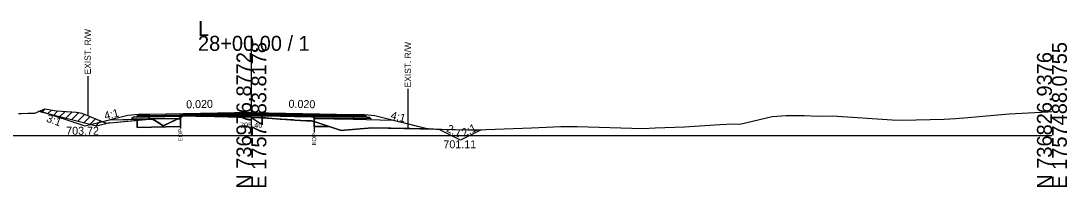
# Model space of a CAD drawing. Extents: x -26 to 4303, y -10 to 9577.
# Drawn here: x 1106.8 to 1302.8, y 7990.3 to 8021.4 of the extents above; entities that cross this region are included whole.
import ezdxf

# ---------------------------------------------------------------- set-up
doc = ezdxf.new("R2010")
doc.units = 0
for name, color, linetype in [('Exist CMT Pavement', 7, 'Continuous'), ('Old_Level_10', 7, 'Continuous'), ('Old_Level_2', 7, 'Continuous'), ('Pattern 1', 7, 'Continuous'), ('Prop CMT Conc Surface', 7, 'Continuous'), ('Prop CMT Concrete Structures', 7, 'Continuous'), ('Prop CMT Concrete Wall', 7, 'Continuous'), ('Prop CMT Pvmt Course 1', 7, 'Continuous'), ('Prop CMT Pvmt Course 1 CG', 7, 'Continuous'), ('Prop CMT Pvmt Course 1 Wedge', 7, 'Continuous'), ('Prop CMT Pvmt Course 2', 7, 'Continuous'), ('Prop CMT Pvmt Course 2 Wedge', 7, 'Continuous'), ('Prop CMT Pvmt Course 3', 7, 'Continuous'), ('Prop CMT Pvmt Surface', 7, 'Continuous'), ('Prop CMT Pvmt Surface Shoulder', 7, 'Continuous'), ('Prop CMT Pvmt Wedge Surface 1', 7, 'Continuous'), ('Prop CMT Pvmt Wedge Surface 2', 7, 'Continuous'), ('Prop CMT Pvmt Wedge Surface 3', 7, 'Continuous'), ('Prop CMT Shld Paved Course 1', 7, 'Continuous'), ('Prop CMT Shld Paved Course 2', 7, 'Continuous'), ('Prop CMT Shld Paved Course 3', 7, 'Continuous'), ('Prop CMT Slope Grass', 7, 'Continuous'), ('Prop CMT Subgrade Earthwork', 7, 'Continuous'), ('Prop Road Sect_ Recs - UC Shallow (Outline)', 7, 'Continuous'), ('Prop Shade Light', 7, 'Continuous'), ('Prop XS DDE Elevations', 7, 'Continuous'), ('Prop XS Ditch Standard Text', 7, 'Continuous'), ('Prop XS Earthwork Shape', 7, 'Continuous'), ('Prop XS Hydro Elevations', 7, 'Continuous'), ('Prop XS SE Text', 7, 'Continuous'), ('Prop XS Side Slope Text', 7, 'Continuous'), ('Prop XS Wedging', 7, 'Continuous')]:
    doc.layers.add(name, color=color, linetype=linetype)

msp = doc.modelspace()

# ---------------------------------------------------------------- linework, layer by layer
at = {"layer": 'Exist CMT Pavement'}
for points in [[(1150, 8004.31), (1130.87, 8003.92)], [(1150, 8004.31), (1169.11, 8003.92)]]:
    msp.add_lwpolyline(points, dxfattribs=at)
at = {"layer": 'Old_Level_10'}
for p, q in [((1185.19, 8001.1), (1183.19, 8001.2)), ((1189.18, 7999.11), (1185.19, 8001.1)), ((1193.07, 8001.05), (1189.18, 7999.11))]:
    msp.add_line(p, q, dxfattribs=at)
at = {"layer": 'Old_Level_2'}
for p, q in [((1150, 8000), (1150, 8018.64)), ((1150, 8000), (1150, 8018.64)), ((1000, 8000), (1150, 8000)), ((1000, 8000), (1150, 8000)), ((1150, 8000), (1300, 8000)), ((1150, 8000), (1300, 8000))]:
    msp.add_line(p, q, dxfattribs=at)
at = {"layer": 'Pattern 1'}
for p, q in [((1110.66, 8004.3), (1111.27, 8004.92)), ((1111.79, 8004.02), (1112.52, 8004.75)), ((1112.92, 8003.74), (1113.76, 8004.57)), ((1114.05, 8003.45), (1115.09, 8004.49)), ((1115.18, 8003.17), (1116.43, 8004.42)), ((1116.32, 8002.89), (1117.7, 8004.28)), ((1117.45, 8002.6), (1118.79, 8003.94)), ((1118.58, 8002.32), (1119.78, 8003.53)), ((1119.71, 8002.04), (1120.78, 8003.11)), ((1120.84, 8001.76), (1121.78, 8002.7)), ((1122.62, 8002.12), (1122.78, 8002.28))]:
    msp.add_line(p, q, dxfattribs=at)
msp.add_lwpolyline([(1121, 8001.72), (1110.11, 8004.44), (1111.33, 8004.94), (1113.49, 8004.59), (1116.23, 8004.43), (1117.2, 8004.37), (1118.22, 8004.18), (1122.8, 8002.27), (1123.44, 8002.33)], close=True, dxfattribs=at)
msp.add_lwpolyline([(1136.69, 8003.35), (1136.69, 8003.11), (1136.19, 8003.1), (1136.69, 8003.35)], dxfattribs=at)
at = {"layer": 'Prop CMT Conc Surface'}
for points in [[(1136.69, 8003.79), (1130.87, 8003.67)], [(1130.87, 8003.67), (1130.87, 8003.47)], [(1130.87, 8003.47), (1136.69, 8003.58)], [(1136.69, 8003.58), (1136.69, 8003.79)], [(1161.75, 8003.61), (1161.75, 8003.82)], [(1161.75, 8003.82), (1169.11, 8003.67)], [(1169.11, 8003.47), (1161.75, 8003.61)], [(1169.11, 8003.67), (1169.11, 8003.47)]]:
    msp.add_lwpolyline(points, dxfattribs=at)
at = {"layer": 'Prop CMT Concrete Structures'}
for points in [[(1130.87, 8003.67), (1130.87, 8003.92)], [(1136.69, 8003.79), (1130.87, 8003.67)], [(1150, 8004.18), (1136.69, 8003.91)], [(1136.69, 8003.91), (1136.69, 8003.79)], [(1150, 8004.18), (1161.75, 8003.95)], [(1161.75, 8003.95), (1161.75, 8003.82)], [(1161.75, 8003.82), (1169.11, 8003.67)], [(1169.11, 8003.67), (1169.11, 8003.92)]]:
    msp.add_lwpolyline(points, dxfattribs=at)
at = {"layer": 'Prop CMT Pvmt Course 1'}
for points in [[(1136.69, 8003.58), (1130.87, 8003.47)], [(1136.69, 8003.25), (1136.69, 8003.58)], [(1161.75, 8003.61), (1169.11, 8003.47)], [(1161.75, 8003.15), (1161.75, 8003.61)], [(1130.87, 8003.47), (1130.87, 8003.13)], [(1130.87, 8003.13), (1136.69, 8003.25)], [(1169.11, 8003.13), (1161.75, 8003.28)], [(1169.11, 8003.47), (1169.11, 8003.13)]]:
    msp.add_lwpolyline(points, dxfattribs=at)
at = {"layer": 'Prop CMT Pvmt Course 1 Wedge'}
for points in [[(1141.82, 8003.56), (1143.12, 8003.59)], [(1150, 8003.4), (1149.52, 8003.45), (1148.34, 8003.42), (1148.13, 8003.42), (1148.13, 8003.42), (1148.11, 8003.42), (1147.61, 8003.43), (1145.68, 8003.47), (1145.63, 8003.47), (1143.25, 8003.54), (1143.12, 8003.55), (1141.82, 8003.56)], [(1143.12, 8003.59), (1143.25, 8003.59), (1145.63, 8003.64), (1145.68, 8003.64), (1147.61, 8003.68), (1148.11, 8003.69), (1148.13, 8003.69), (1148.13, 8003.69), (1148.34, 8003.69), (1149.52, 8003.72), (1150, 8003.73)], [(1150, 8003.73), (1150, 8003.4)], [(1150, 8003.73), (1150.15, 8003.72), (1150.34, 8003.72), (1150.62, 8003.71), (1150.63, 8003.71), (1152.98, 8003.67), (1153.13, 8003.66), (1155.41, 8003.62), (1155.63, 8003.61), (1157.84, 8003.57), (1158.13, 8003.56), (1160.27, 8003.52), (1160.63, 8003.51), (1160.66, 8003.51), (1161.24, 8003.5), (1161.44, 8003.5), (1161.54, 8003.5), (1161.75, 8003.49)], [(1161.75, 8003.49), (1161.75, 8002.57)], [(1136.69, 8003.46), (1136.92, 8003.46)], [(1136.92, 8003.46), (1136.69, 8003.35)], [(1136.69, 8003.35), (1136.69, 8003.46)], [(1161.75, 8002.57), (1161.54, 8002.64), (1161.44, 8002.64), (1161.24, 8002.7), (1160.66, 8002.72), (1160.63, 8002.72), (1160.27, 8002.74), (1158.13, 8002.86), (1157.84, 8002.88), (1155.63, 8003.05), (1155.41, 8003.06), (1153.13, 8003.2), (1152.98, 8003.21), (1150.63, 8003.34), (1150.62, 8003.34), (1150.34, 8003.37), (1150.15, 8003.39), (1150, 8003.4)]]:
    msp.add_lwpolyline(points, dxfattribs=at)
at = {"layer": 'Prop CMT Pvmt Course 2'}
for points in [[(1130.87, 8003.92), (1128.87, 8003.88), (1128.62, 8003.63)], [(1128.62, 8003.63), (1130.87, 8003.67)], [(1130.87, 8003.67), (1130.87, 8003.92)], [(1169.11, 8003.92), (1171.11, 8003.88), (1171.36, 8003.63)], [(1169.11, 8003.67), (1169.11, 8003.92)], [(1171.36, 8003.63), (1169.11, 8003.67)]]:
    msp.add_lwpolyline(points, dxfattribs=at)
at = {"layer": 'Prop CMT Pvmt Course 2 Wedge'}
msp.add_line((1118.87, 8001.72), (1110.38, 8004.55), dxfattribs=at)
for points in [[(1128.87, 8003.88), (1126.87, 8003.72), (1118.87, 8001.72)], [(1171.11, 8003.88), (1173.11, 8003.72), (1183.19, 8001.2)]]:
    msp.add_lwpolyline(points, dxfattribs=at)
at = {"layer": 'Prop CMT Pvmt Course 3'}
for points in [[(1130.87, 8003.67), (1128.62, 8003.63), (1128.4, 8003.42)], [(1130.87, 8003.47), (1130.87, 8003.67)], [(1169.11, 8003.67), (1171.36, 8003.63), (1171.58, 8003.42)], [(1169.11, 8003.47), (1169.11, 8003.67)], [(1128.4, 8003.42), (1130.87, 8003.47)], [(1171.58, 8003.42), (1169.11, 8003.47)]]:
    msp.add_lwpolyline(points, dxfattribs=at)
at = {"layer": 'Prop CMT Pvmt Surface'}
for points in [[(1150, 8004.06), (1130.87, 8003.67)], [(1130.87, 8003.67), (1130.87, 8003.92)], [(1150, 8004.06), (1169.11, 8003.67)], [(1169.11, 8003.67), (1169.11, 8003.92)]]:
    msp.add_lwpolyline(points, dxfattribs=at)
at = {"layer": 'Prop CMT Pvmt Surface Shoulder'}
for points in [[(1136.69, 8003.35), (1137.27, 8003.64), (1137.54, 8003.64), (1138.03, 8003.66), (1140.6, 8003.58), (1140.62, 8003.58), (1140.82, 8003.58), (1143.12, 8003.55), (1143.25, 8003.54), (1145.63, 8003.47), (1145.68, 8003.47), (1147.61, 8003.43), (1148.11, 8003.42), (1148.13, 8003.42), (1148.13, 8003.42), (1148.34, 8003.42), (1149.52, 8003.45), (1150, 8003.4)], [(1150, 8003.4), (1150.15, 8003.39), (1150.34, 8003.37), (1150.62, 8003.34), (1150.63, 8003.34), (1152.98, 8003.21), (1153.13, 8003.2), (1155.41, 8003.06), (1155.63, 8003.05), (1157.84, 8002.88), (1158.13, 8002.86), (1160.27, 8002.74), (1160.63, 8002.72), (1160.66, 8002.72), (1161.24, 8002.7), (1161.44, 8002.64), (1161.54, 8002.64), (1161.75, 8002.57)]]:
    msp.add_lwpolyline(points, dxfattribs=at)
at = {"layer": 'Prop CMT Pvmt Wedge Surface 1'}
for p, q in [((1130.89, 8003.01), (1123.41, 8002.86)), ((1136.69, 8003.12), (1130.89, 8003.01)), ((1161.75, 8003.15), (1169.09, 8003.01)), ((1169.09, 8003.01), (1176.57, 8002.86))]:
    msp.add_line(p, q, dxfattribs=at)
for points in [[(1136.69, 8003.12), (1136.69, 8003.35)], [(1161.75, 8003.15), (1161.75, 8002.57)]]:
    msp.add_lwpolyline(points, dxfattribs=at)
at = {"layer": 'Prop CMT Pvmt Wedge Surface 2'}
for points in [[(1136.69, 8003.91), (1137.27, 8003.93), (1137.54, 8003.93), (1138.03, 8003.94), (1140.6, 8003.99), (1140.62, 8003.99), (1140.82, 8004), (1143.12, 8004.04), (1143.25, 8004.05), (1145.63, 8004.09), (1145.68, 8004.09), (1147.61, 8004.13), (1148.11, 8004.14), (1148.13, 8004.14), (1148.13, 8004.14), (1148.34, 8004.15), (1149.52, 8004.17), (1150, 8004.18)], [(1136.69, 8003.47), (1136.69, 8003.91)], [(1150, 8004.06), (1149.52, 8004.05), (1148.34, 8004.02), (1148.13, 8004.02), (1148.13, 8004.02), (1148.11, 8004.02), (1147.61, 8004.01), (1145.68, 8003.97), (1145.63, 8003.97), (1143.25, 8003.92), (1143.12, 8003.92), (1142.01, 8003.9)], [(1150, 8004.18), (1150, 8004.06)], [(1150, 8004.18), (1150.15, 8004.18), (1150.34, 8004.17), (1150.62, 8004.17), (1150.63, 8004.17), (1152.98, 8004.12), (1153.13, 8004.12), (1155.41, 8004.07), (1155.63, 8004.07), (1157.84, 8004.02), (1158.13, 8004.02), (1160.27, 8003.98), (1160.63, 8003.97), (1160.66, 8003.97), (1161.24, 8003.96), (1161.44, 8003.95), (1161.54, 8003.95), (1161.75, 8003.95)], [(1161.75, 8003.82), (1161.54, 8003.83), (1161.44, 8003.83), (1161.24, 8003.83), (1160.66, 8003.84), (1160.63, 8003.84), (1160.27, 8003.85), (1158.13, 8003.89), (1157.84, 8003.9), (1155.63, 8003.94), (1155.41, 8003.95), (1153.13, 8003.99), (1152.98, 8004), (1150.63, 8004.04), (1150.62, 8004.04), (1150.34, 8004.05), (1150.15, 8004.05), (1150, 8004.06)], [(1161.75, 8003.95), (1161.75, 8002.69)]]:
    msp.add_lwpolyline(points, dxfattribs=at)
at = {"layer": 'Prop CMT Pvmt Wedge Surface 3'}
for points in [[(1136.69, 8003.79), (1137.27, 8003.8), (1137.54, 8003.81), (1138.03, 8003.82), (1140.6, 8003.87), (1140.62, 8003.87), (1140.82, 8003.87), (1143.12, 8003.92), (1143.25, 8003.92), (1145.63, 8003.97), (1145.68, 8003.97), (1147.61, 8004.01), (1148.11, 8004.02), (1148.13, 8004.02), (1148.13, 8004.02), (1148.34, 8004.02), (1149.52, 8004.05), (1150, 8004.06)], [(1150, 8003.85), (1149.52, 8003.84), (1148.34, 8003.81), (1148.13, 8003.81), (1148.13, 8003.81), (1148.11, 8003.81), (1147.61, 8003.8), (1145.68, 8003.76), (1145.63, 8003.76), (1143.25, 8003.71), (1143.12, 8003.71), (1141.82, 8003.68), (1140.82, 8003.7), (1140.62, 8003.7), (1140.6, 8003.7), (1138.03, 8003.78), (1137.54, 8003.76), (1137.27, 8003.76), (1136.92, 8003.59), (1136.69, 8003.58)], [(1136.69, 8003.58), (1136.69, 8003.79)], [(1150, 8004.06), (1150, 8003.85)], [(1150, 8004.06), (1150.15, 8004.05), (1150.34, 8004.05), (1150.62, 8004.04), (1150.63, 8004.04), (1152.98, 8004), (1153.13, 8003.99), (1155.41, 8003.95), (1155.63, 8003.94), (1157.84, 8003.9), (1158.13, 8003.89), (1160.27, 8003.85), (1160.63, 8003.84), (1160.66, 8003.84), (1161.24, 8003.83), (1161.44, 8003.83), (1161.54, 8003.83), (1161.75, 8003.82)], [(1161.75, 8003.61), (1161.54, 8003.62), (1161.44, 8003.62), (1161.24, 8003.62), (1160.66, 8003.63), (1160.63, 8003.64), (1160.27, 8003.64), (1158.13, 8003.69), (1157.84, 8003.69), (1155.63, 8003.74), (1155.41, 8003.74), (1153.13, 8003.79), (1152.98, 8003.79), (1150.63, 8003.84), (1150.62, 8003.84), (1150.34, 8003.84), (1150.15, 8003.84), (1150, 8003.85)], [(1161.75, 8003.82), (1161.75, 8003.61)]]:
    msp.add_lwpolyline(points, dxfattribs=at)
at = {"layer": 'Prop CMT Shld Paved Course 1'}
for points in [[(1130.87, 8003.47), (1130.87, 8003.92)], [(1150, 8003.85), (1130.87, 8003.47)], [(1150, 8003.85), (1169.11, 8003.47)], [(1169.11, 8003.47), (1169.11, 8003.92)]]:
    msp.add_lwpolyline(points, dxfattribs=at)
at = {"layer": 'Prop CMT Shld Paved Course 2'}
for points in [[(1130.87, 8003.92), (1128.87, 8003.88)], [(1169.11, 8003.92), (1171.11, 8003.88)]]:
    msp.add_lwpolyline(points, dxfattribs=at)
at = {"layer": 'Prop CMT Shld Paved Course 3'}
for points in [[(1150, 8004.31), (1130.87, 8003.92)], [(1130.87, 8003.92), (1130.87, 8003.67)], [(1130.87, 8003.67), (1136.69, 8003.79)], [(1136.69, 8003.91), (1150, 8004.18)], [(1136.69, 8003.79), (1136.69, 8003.91)], [(1150, 8004.31), (1169.11, 8003.92)], [(1161.75, 8003.95), (1150, 8004.18)], [(1161.75, 8003.82), (1161.75, 8003.95)], [(1169.11, 8003.67), (1161.75, 8003.82)], [(1169.11, 8003.92), (1169.11, 8003.67)]]:
    msp.add_lwpolyline(points, dxfattribs=at)
at = {"layer": 'Prop CMT Slope Grass'}
msp.add_lwpolyline([(1106.39, 8004.1), (1106.91, 8004.08), (1108.14, 8004.13), (1109.43, 8004.16), (1111.33, 8004.94), (1113.49, 8004.59), (1117.21, 8004.37), (1118.22, 8004.18), (1122.8, 8002.27), (1124.18, 8002.39), (1130.61, 8003.03), (1131.45, 8003.05), (1132.65, 8002.33), (1133.5, 8001.77), (1133.92, 8001.98), (1137.27, 8003.64), (1138.03, 8003.66), (1139.61, 8003.61), (1140.03, 8003.59), (1140.82, 8003.58), (1143.25, 8003.54), (1145.68, 8003.47), (1147.61, 8003.43), (1148.34, 8003.42), (1149.52, 8003.45), (1150.63, 8003.34), (1153.13, 8003.2), (1155.63, 8003.05), (1158.13, 8002.86), (1160.27, 8002.74), (1160.66, 8002.72), (1161.24, 8002.7), (1161.54, 8002.64), (1162.87, 8002.22), (1166.82, 8000.88), (1167.46, 8000.95), (1172.63, 8001.43), (1190.53, 8001.04), (1191.92, 8001.02), (1192.24, 8001.03), (1202.51, 8001.38), (1208, 8001.65), (1210.15, 8001.67), (1211.07, 8001.67), (1223.36, 8001.29), (1225.68, 8001.39), (1231.13, 8001.61), (1237.76, 8002.04), (1240.34, 8002.14), (1241.54, 8002.1), (1247.57, 8003.54), (1250.23, 8003.72), (1253.63, 8003.71), (1256.06, 8003.58), (1258.91, 8003.64), (1270.07, 8002.91), (1271.96, 8002.86), (1279.8, 8003.06), (1281.96, 8003.16), (1284.26, 8003.34), (1291.97, 8004.05), (1299.25, 8004.39), (1300, 8004.47)], dxfattribs=at)
at = {"layer": 'Prop CMT Subgrade Earthwork'}
for points in [[(1130.87, 8003.47), (1128.4, 8003.42), (1127.9, 8003.41), (1127.56, 8003.07)], [(1127.56, 8003.07), (1130.87, 8003.13)], [(1130.87, 8003.13), (1130.87, 8003.47)], [(1169.11, 8003.47), (1171.58, 8003.42), (1172.08, 8003.41), (1172.42, 8003.07)], [(1169.11, 8003.13), (1169.11, 8003.47)], [(1172.42, 8003.07), (1169.11, 8003.13)]]:
    msp.add_lwpolyline(points, dxfattribs=at)
at = {"layer": 'Prop Road Sect_ Recs - UC Shallow (Outline)'}
for p, q in [((1161.75, 8001.66), (1161.75, 8002.58)), ((1164.54, 8001.65), (1161.75, 8001.66))]:
    msp.add_line(p, q, dxfattribs=at)
msp.add_lwpolyline([(1128.61, 8001.49), (1128.61, 8002.83), (1130.14, 8002.98), (1131.51, 8003.01), (1133.5, 8001.77), (1136.19, 8003.1), (1136.69, 8003.11), (1136.69, 8001.63)], close=True, dxfattribs=at)
msp.add_lwpolyline([(1164.54, 8001.65), (1162.87, 8002.22), (1161.75, 8002.57)], dxfattribs=at)
at = {"layer": 'Prop Shade Light'}
for p, q in [((1130.14, 8002.98), (1128.61, 8002.83)), ((1128.61, 8002.83), (1128.61, 8001.49)), ((1128.61, 8001.49), (1136.69, 8001.63)), ((1130.88, 8003), (1130.14, 8002.98)), ((1131.51, 8003.01), (1130.88, 8003)), ((1136.19, 8003.1), (1133.5, 8001.77)), ((1136.69, 8003.11), (1136.19, 8003.1)), ((1136.69, 8001.63), (1136.69, 8003.11)), ((1162.87, 8002.22), (1161.75, 8002.57)), ((1161.75, 8002.57), (1161.75, 8001.66)), ((1161.75, 8001.66), (1164.54, 8001.65)), ((1164.54, 8001.65), (1162.87, 8002.22))]:
    msp.add_line(p, q, dxfattribs=at)
for points in [[(1133.5, 8001.77), (1132.65, 8002.33), (1131.51, 8003.01)], [(1136.19, 8003.1), (1136.19, 8003.1), (1136.19, 8003.1)]]:
    msp.add_lwpolyline(points, dxfattribs=at)
at = {"layer": 'Prop XS DDE Elevations'}
for points in [[(1113.49, 8004.59), (1117.21, 8004.37), (1118.22, 8004.18), (1122.15, 8002.54), (1118.87, 8001.72), (1110.38, 8004.55), (1111.33, 8004.94)], [(1137.27, 8003.64), (1137.54, 8003.64), (1138.03, 8003.66)], [(1139.61, 8003.61), (1140.03, 8003.59), (1140.62, 8003.58), (1140.6, 8003.58), (1138.03, 8003.66)], [(1140.82, 8003.58), (1143.12, 8003.55), (1143.25, 8003.54)], [(1130.24, 8002.99), (1123.41, 8002.86), (1122.15, 8002.54), (1122.8, 8002.27), (1124.18, 8002.39)], [(1130.89, 8003.01), (1130.24, 8002.99), (1130.61, 8003.03), (1131.45, 8003.05), (1131.5, 8003.02)], [(1132.65, 8002.33), (1133.5, 8001.77), (1133.92, 8001.98), (1136.21, 8003.11), (1131.5, 8003.02)], [(1136.21, 8003.11), (1136.69, 8003.35), (1136.69, 8003.12)], [(1147.61, 8003.43), (1148.34, 8003.42), (1148.13, 8003.42), (1148.11, 8003.42)], [(1149.52, 8003.45), (1150.6, 8003.34), (1150.34, 8003.37), (1150.15, 8003.39), (1150, 8003.4)], [(1157.84, 8002.88), (1158.13, 8002.86), (1155.63, 8003.05)], [(1160.27, 8002.74), (1160.63, 8002.72), (1160.66, 8002.72)], [(1161.24, 8002.7), (1161.54, 8002.64), (1161.44, 8002.64)], [(1169.09, 8003.01), (1176.57, 8002.86), (1183.19, 8001.2), (1172.63, 8001.43), (1167.46, 8000.95), (1166.82, 8000.88), (1162.87, 8002.22), (1161.75, 8002.57), (1161.75, 8003.15)]]:
    msp.add_lwpolyline(points, close=True, dxfattribs=at)
at = {"layer": 'Prop XS Ditch Standard Text'}
for p, q in [((1119.33, 8011.12), (1119.33, 8003.72)), ((1179.33, 8008.69), (1179.33, 8001.29)), ((1136.69, 8003.35), (1136.69, 8001.3)), ((1161.75, 8002.57), (1161.75, 8000.52))]:
    msp.add_line(p, q, dxfattribs=at)
at = {"layer": 'Prop XS Earthwork Shape'}
msp.add_lwpolyline([(1193.07, 8001.05), (1189.18, 7999.11), (1185.19, 8001.1), (1183.19, 8001.2), (1190.53, 8001.04), (1191.92, 8001.02), (1192.24, 8001.03)], close=True, dxfattribs=at)
at = {"layer": 'Prop XS Wedging'}
for p, q in [((1150, 8004.18), (1136.69, 8003.91)), ((1136.69, 8003.91), (1136.69, 8003.79)), ((1136.69, 8003.79), (1136.69, 8003.58)), ((1136.69, 8003.58), (1136.69, 8003.48)), ((1139.18, 8003.84), (1138.98, 8003.63)), ((1138.98, 8003.63), (1139.18, 8003.84)), ((1139.18, 8003.84), (1138.98, 8003.63)), ((1139.18, 8003.84), (1150, 8004.06)), ((1139.18, 8003.84), (1150, 8004.06)), ((1147.98, 8003.68), (1147.74, 8003.43)), ((1147.74, 8003.43), (1147.98, 8003.68)), ((1147.98, 8003.68), (1147.74, 8003.43)), ((1147.98, 8003.68), (1150.01, 8003.72)), ((1147.98, 8003.68), (1149.99, 8003.72)), ((1161.75, 8003.49), (1149.99, 8003.72)), ((1149.99, 8003.72), (1150, 8003.72)), ((1161.75, 8003.95), (1150, 8004.18)), ((1161.75, 8003.82), (1150, 8004.06)), ((1150, 8004.06), (1150, 8004.06)), ((1150, 8004.06), (1150, 8004.06)), ((1150, 8004.06), (1161.75, 8003.82)), ((1150, 8003.72), (1150.01, 8003.72)), ((1150.01, 8003.72), (1161.75, 8003.49)), ((1161.75, 8003.82), (1161.75, 8003.95)), ((1161.75, 8003.61), (1161.75, 8003.82)), ((1161.75, 8003.49), (1161.75, 8003.61)), ((1136.69, 8003.48), (1136.69, 8003.35))]:
    msp.add_line(p, q, dxfattribs=at)
for points in [[(1136.69, 8003.35), (1137.27, 8003.64), (1138.03, 8003.66), (1138.98, 8003.63)], [(1138.98, 8003.63), (1139.61, 8003.61), (1140.03, 8003.59), (1140.82, 8003.58), (1143.25, 8003.54), (1145.68, 8003.47), (1147.61, 8003.43), (1147.74, 8003.43), (1147.74, 8003.43)], [(1150, 8004.06), (1150, 8004.06), (1139.18, 8003.84)], [(1150, 8003.72), (1149.99, 8003.72), (1147.98, 8003.68)], [(1149.99, 8003.72), (1149.99, 8003.72)], [(1150, 8004.06), (1150, 8004.06)], [(1150, 8004.06), (1150, 8004.06)], [(1161.75, 8003.82), (1150, 8004.06), (1150, 8004.06)], [(1161.75, 8003.49), (1150.01, 8003.72), (1150, 8003.72)], [(1150.01, 8003.72), (1150.01, 8003.72)], [(1136.69, 8003.48), (1136.69, 8003.48)], [(1147.74, 8003.43), (1148.34, 8003.42), (1149.52, 8003.45), (1150.63, 8003.34), (1153.13, 8003.2), (1155.63, 8003.05), (1158.13, 8002.86), (1160.27, 8002.74), (1160.66, 8002.72), (1161.24, 8002.7), (1161.54, 8002.64), (1161.75, 8002.57)], [(1161.75, 8003.15), (1161.75, 8003.28), (1161.75, 8003.49)], [(1161.75, 8002.57), (1161.75, 8002.58), (1161.75, 8003.15)]]:
    msp.add_lwpolyline(points, dxfattribs=at)

# ---------------------------------------------------------------- texts
at = {"layer": 'Old_Level_2'}
for s, p in [('L', (1140, 8018.64)), ('L', (1140, 8018.64)), ('28+00.00 / 1', (1140, 8015.84)), ('28+00.00 / 1', (1140, 8015.84))]:
    msp.add_text(s, height=2.8, dxfattribs=at).set_placement(p)
for s, p in [('E 1757483.8178', (1152.8, 7990)), ('E 1757483.8178', (1152.8, 7990)), ('E 1757488.0755', (1302.8, 7990)), ('E 1757488.0755', (1302.8, 7990)), ('N 736976.8772', (1150, 7990)), ('N 736976.8772', (1150, 7990)), ('N 736826.9376', (1300, 7990)), ('N 736826.9376', (1300, 7990))]:
    msp.add_text(s, height=2.8, rotation=90, dxfattribs=at).set_placement(p)
at = {"layer": 'Prop CMT Concrete Wall'}
for rotation, p in [(334.1383, (1186.4, 8000.77)), (25.8617, (1189.83, 7999.69))]:
    msp.add_text('2:1', height=1.5, rotation=rotation, dxfattribs=at).set_placement(p)
msp.add_text('701.11', height=1.5, dxfattribs=at).set_placement((1185.98, 7997.57))
at = {"layer": 'Prop CMT Pvmt Course 1 CG'}
msp.add_text('705.40', height=1, dxfattribs=at).set_placement((1147.85, 8001.4))
at = {"layer": 'Prop XS Ditch Standard Text'}
for s, height, p in [('EXIST. R/W', 1.181, (1119.92, 8011.42)), ('EXIST. R/W', 1.181, (1179.92, 8008.99)), ('EOP', 0.787, (1137.08, 7998.9)), ('EOP', 0.787, (1162.14, 7998.12))]:
    msp.add_text(s, height=height, rotation=90, dxfattribs=at).set_placement(p)
at = {"layer": 'Prop XS Hydro Elevations'}
msp.add_text('703.72', height=1.5, dxfattribs=at).set_placement((1115.3, 8000.11))
at = {"layer": 'Prop XS SE Text'}
for rotation, p in [(1.1458, (1137.79, 8005.06)), (358.8542, (1156.95, 8005.17))]:
    msp.add_text('0.020', height=1.5, rotation=rotation, dxfattribs=at).set_placement(p)
at = {"layer": 'Prop XS Side Slope Text'}
for s, rotation, p in [('3:1', 339.8916, (1111.45, 8002.61)), ('4:1', 14.0362, (1122.61, 8002.89)), ('4:1', 345.9638, (1175.99, 8003.11))]:
    msp.add_text(s, height=1.5, rotation=rotation, dxfattribs=at).set_placement(p)

doc.saveas('drawing.dxf')
